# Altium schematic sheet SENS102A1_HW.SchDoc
size 431 x 279 mm; Date: Not shown in title block; ApprovedBy: Not shown in title block; CheckedBy: Not shown in title block; Author: Not shown in title block; CompanyName: Not shown in title block; Engineer: Not shown in title block; Organization: Not shown in title block; Address1: Not shown in title block; Address2: Not shown in title block; Address3: Not shown in title block; Address4: Not shown in title block; DocumentNumber: 3; Revision: Use project parameter SCH_Rev; SheetNumber: 3; SheetTotal: 3; PageSetup: Record=PageOptions¦CenterHorizontal=True¦CenterVertical=True¦PrintScale=1.00¦XCorrection=1.00¦YCorrection=1.00¦PrintKind=0¦BorderSize=5000000¦LeftOffset=0¦BottomOffset=0¦Orientation=2¦PaperLength=1000¦PaperWidth=1000¦Scale=100¦PaperSource=15¦PrintQuality=600¦MediaType=1¦DitherType=10¦PaperKind=Letter¦PrintScaleMode=1
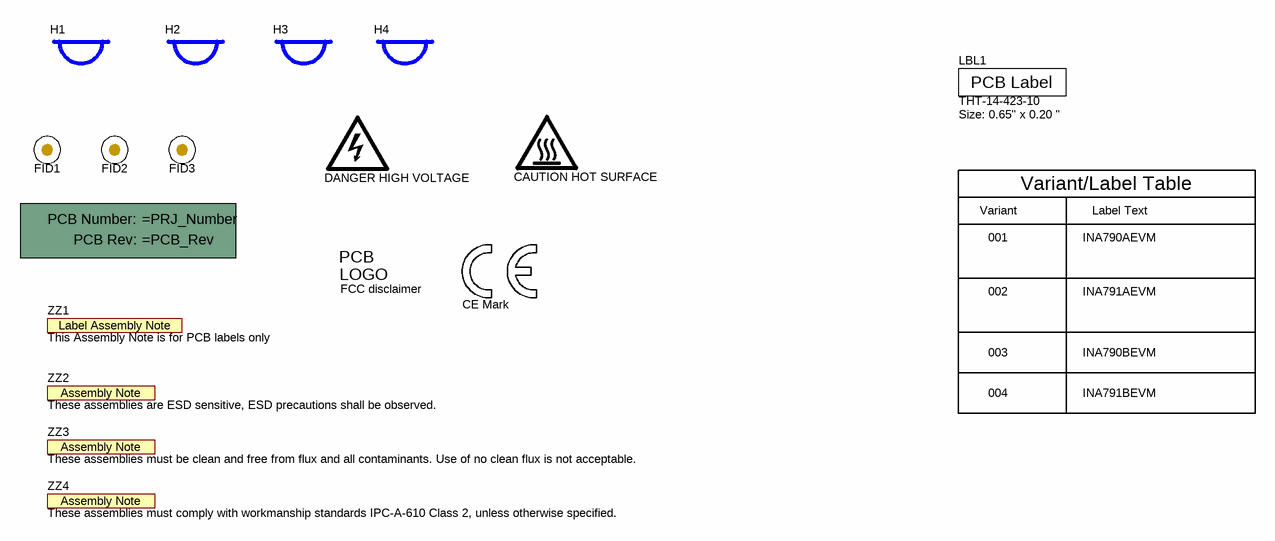
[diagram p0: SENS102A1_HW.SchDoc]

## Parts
!PCB1  Printed Circuit Board  (value not drawn)  (mechanical)
FID1  Fiducial  [Fiducial10-20]  (value not drawn)
FID2  Fiducial  [Fiducial10-20]  (value not drawn)
FID3  Fiducial  [Fiducial10-20]  (value not drawn)
H1  SJ61A2  [Bumpon_SJ61A2]  (value not drawn)
H2  SJ61A2  [Bumpon_SJ61A2]  (value not drawn)
H3  SJ61A2  [Bumpon_SJ61A2]  (value not drawn)
H4  SJ61A2  [Bumpon_SJ61A2]  (value not drawn)
LBL1  THT-14-423-10  Note: Size: 0.65" x 0.20 "  [Label_650x200]
LOGO1  DANGER HIGH VOLTAGE  [IEC_HighVoltage_Medium]  (no BOM)
Logo2  FCC disclaimer  [FCC_disclaimer]  (no BOM)
LOGO3  CE Mark  [CE_Mark_5mm]  (no BOM)
Logo4  CAUTION HOT SURFACE  [IEC_HotSurface_Medium]  (no BOM)
ZZ1  This Assembly Note is for PCB labels only  [AssemblyNoteLabel]  (no BOM)
ZZ2  These assemblies are ESD sensitive, ESD precautions shall be observed.  [AssemblyNote]  (no BOM)
ZZ3  These assemblies must be clean and free from flux and all contaminants. Use of no clean flux is not acceptable.  [AssemblyNote]  (no BOM)
ZZ4  These assemblies must comply with workmanship standards IPC-A-610 Class 2, unless otherwise specified.  [AssemblyNote]  (no BOM)

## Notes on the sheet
- Variant
- Variant/Label Table
- Label Text
- 001
- INA790AEVM
- 002
- 003
- INA791AEVM
- INA790BEVM
- 004
- INA791BEVM

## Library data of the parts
!PCB1 = CMP-0003618-2: Manufacturer: Any
FID1-FID3 = CMP-0077181-1: Fiducial mark.  There is nothing to buy or mount.
H1-H4 = CMP-0003622-1: Bumpon, Hemisphere, 0.375 X 0.235, Black; Manufacturer: 3M
LBL1 = CMP-0003625-1: Thermal Transfer Printable Labels, 0.650" W x 0.200" H - 10,000 per roll; Manufacturer: Brady; CompType: Label
LOGO1 = CMP-0074835-1: IEC 61010-1 High Voltage Warning; SymbolCreator: a0412235
Logo2 = CMP-0074847-1: FCC_disclaimer
LOGO3 = CMP-0074844-1: SymbolCreator: a0412235
Logo4 = CMP-0074837-2: IEC 61010-1 Hot Surface Warning; Manufacturer: Texas Instruments; CompType: IC; AEC Category: Q200; SymbolCreator: a0412235
ZZ1 = CMP-0003616-3
ZZ2 = CMP-0077236-1
ZZ3 = CMP-0077237-1
ZZ4 = CMP-0077238-1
